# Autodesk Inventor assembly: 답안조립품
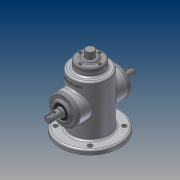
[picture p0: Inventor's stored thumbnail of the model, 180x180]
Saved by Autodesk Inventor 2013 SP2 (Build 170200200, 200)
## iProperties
Created: 2014-12
Part Number: 답안조립품
Document SubType Name: Assembly
Designer: CADB202
Author: CADB202
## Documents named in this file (12)
- C:\Users\CADB202\Desktop\441228V1017\답안조립품.iam
- C:\Users\CADB202\Desktop\441228V1017\본체.ipt
- C:\Users\CADB202\Desktop\441228V1017\M3x0.5x8.ipt
- M3x0.5.ipt
- C:\Users\CADB202\Desktop\441228V1017\베어링 6002.ipt
- 베어링 6002.ipt
- C:\Users\CADB202\Desktop\441228V1017\상단커버.ipt
- C:\Users\CADB202\Desktop\441228V1017\슬라이드.ipt
- C:\Users\CADB202\Desktop\441228V1017\오일실.ipt
- 오일실.ipt
- C:\Users\CADB202\Desktop\441228V1017\커버.ipt
- C:\Users\CADB202\Desktop\441228V1017\편심축.ipt
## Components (12 placed, 1 different names)
1. M3x0.5:2 — 각도:2
2. M3x0.5:1 — 각도:1
3. M3x0.5:3
4. M3x0.5:4
5. M3x0.5:5
6. M3x0.5:6
7. M3x0.5:7
8. M3x0.5:8
9. M3x0.5:9 — 각도:3
10. M3x0.5:10
11. M3x0.5:11
12. M3x0.5:12
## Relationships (3: Angle 3)
- 각도:1 [Angle]: M3x0.5:1
- 각도:2 [Angle]: M3x0.5:2
- 각도:3 [Angle]: M3x0.5:9
